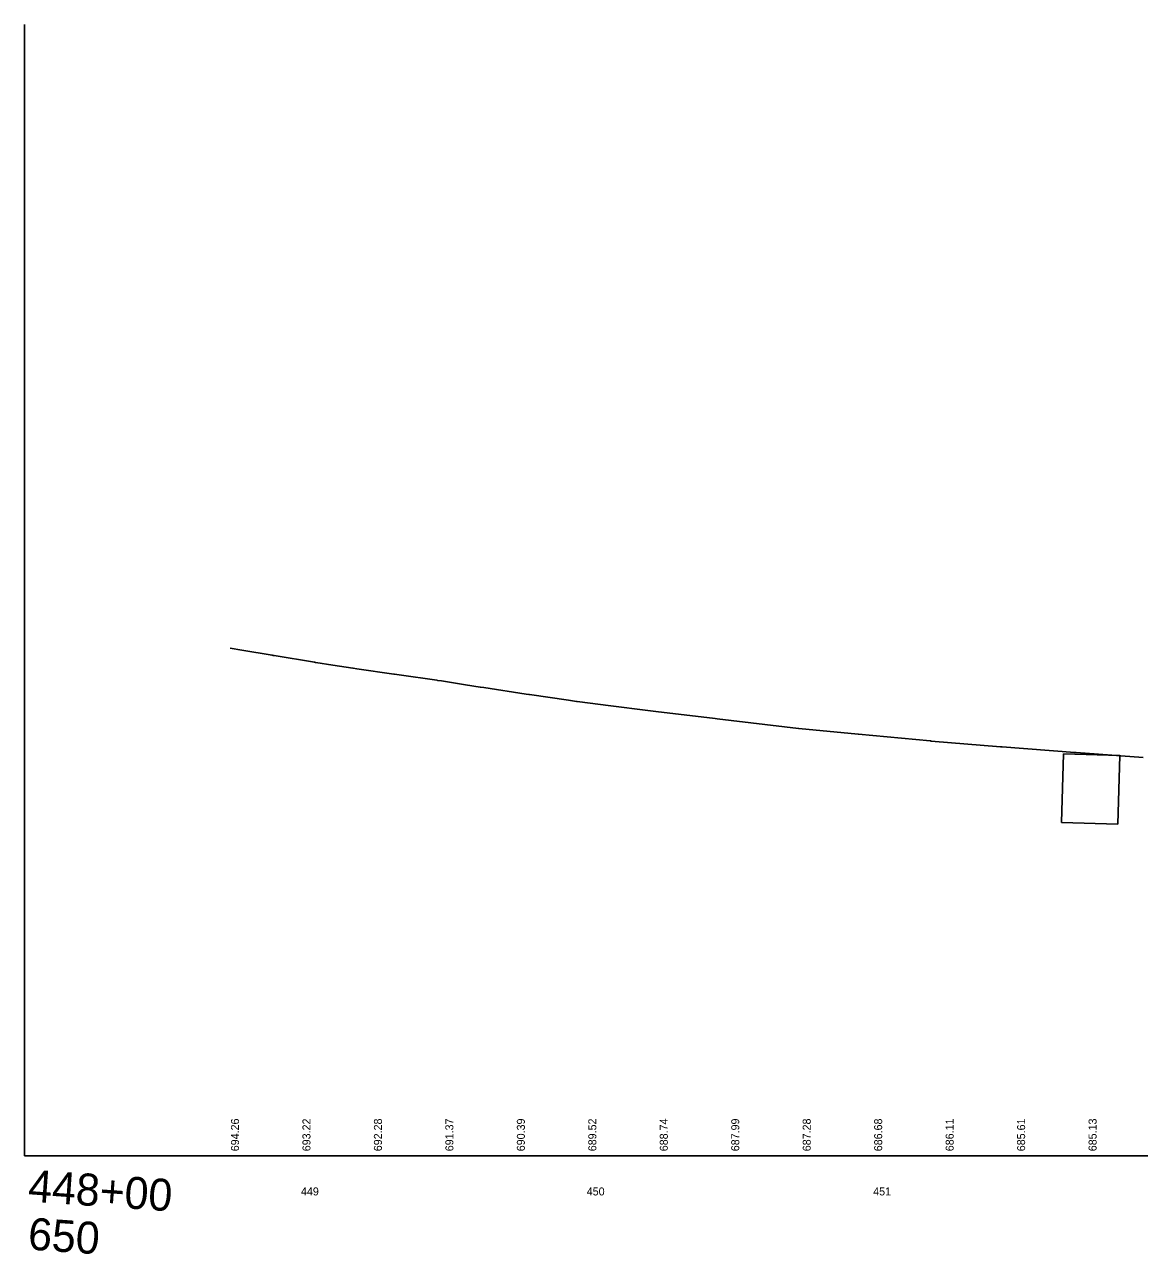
# Model space of a CAD drawing. Extents: x 157201 to 163282, y 424960 to 427200.
# Drawn here: x 161406.3 to 161796.3, y 425928.9 to 426359.1 of the extents above; entities that cross this region are included whole.
import ezdxf

# ---------------------------------------------------------------- set-up
doc = ezdxf.new("R2010")
doc.units = 0
for name, color, linetype in [('DR_X_Elev_Flow', 7, 'Continuous'), ('RD_X_Fence', 7, 'Continuous'), ('RD_X_GR_Rt', 7, 'Continuous'), ('SV_X_Shot_Marker', 7, 'Continuous'), ('UT_X_Water_Cells', 7, 'Continuous')]:
    doc.layers.add(name, color=color, linetype=linetype)

msp = doc.modelspace()

# ---------------------------------------------------------------- linework, layer by layer
at = {"layer": 'DR_X_Elev_Flow'}
for p, q in [((161769.01, 426079.96), (161769.74, 426103.95)), ((161769.74, 426103.95), (161789.44, 426103.35)), ((161788.71, 426079.36), (161789.44, 426103.35)), ((161769.01, 426079.96), (161788.71, 426079.36))]:
    msp.add_line(p, q, dxfattribs=at)
at = {"layer": 'SV_X_Shot_Marker'}
for q in [(161406.29, 426359.06), (162615.86, 425963.36)]:
    msp.add_line((161406.29, 425963.36), q, dxfattribs=at)
at = {"layer": 'UT_X_Water_Cells'}
msp.add_lwpolyline([(161478.17, 426140.9), (161482.27, 426140.23), (161492.93, 426138.44), (161493.22, 426138.39), (161493.48, 426138.34), (161493.56, 426138.33), (161507.74, 426136.02), (161508.07, 426135.96), (161508.12, 426135.95), (161508.15, 426135.94), (161514.08, 426135.05), (161521.08, 426133.96), (161521.17, 426133.94), (161521.27, 426133.93), (161522.55, 426133.75), (161535.5, 426131.87), (161535.69, 426131.84), (161537.37, 426131.62), (161550.48, 426129.72), (161550.6, 426129.7), (161550.73, 426129.69), (161552.18, 426129.47), (161560.53, 426128.16), (161565.7, 426127.33), (161565.71, 426127.33), (161565.72, 426127.33), (161565.73, 426127.33), (161566.99, 426127.14), (161581.8, 426124.85), (161582.63, 426124.72), (161582.69, 426124.72), (161582.76, 426124.72), (161582.87, 426124.71), (161596.61, 426122.74), (161599.38, 426122.33), (161599.41, 426122.32), (161599.64, 426122.29), (161611.42, 426120.82), (161624.35, 426119.17), (161627.08, 426118.84), (161647.91, 426116.32), (161648.51, 426116.25), (161677.07, 426112.9), (161677.13, 426112.9), (161697.86, 426110.86), (161698.05, 426110.84), (161723.08, 426108.5), (161723.23, 426108.48), (161723.37, 426108.47), (161747.7, 426106.44), (161747.73, 426106.44), (161748.23, 426106.41), (161773.66, 426104.43), (161774.19, 426104.4), (161797.53, 426102.67)], dxfattribs=at)

# ---------------------------------------------------------------- texts
at = {"layer": 'RD_X_Fence'}
for s, p in [('694.26', (161481.29, 425964.97)), ('693.22', (161506.29, 425964.97)), ('692.28', (161531.29, 425964.97)), ('691.37', (161556.29, 425964.97)), ('690.39', (161581.29, 425964.97)), ('689.52', (161606.29, 425964.97)), ('688.74', (161631.29, 425964.97)), ('687.99', (161656.29, 425964.97)), ('687.28', (161681.29, 425964.97)), ('686.68', (161706.29, 425964.97)), ('686.11', (161731.29, 425964.97)), ('685.61', (161756.29, 425964.97)), ('685.13', (161781.29, 425964.97))]:
    msp.add_text(s, height=2.8, rotation=90, dxfattribs=at).set_placement(p)
at = {"layer": 'RD_X_GR_Rt'}
for s, p in [('449', (161502.97, 425949.52)), ('450', (161602.94, 425949.52)), ('451', (161703.14, 425949.52))]:
    msp.add_text(s, height=2.8, dxfattribs=at).set_placement(p)
at = {"layer": 'SV_X_Shot_Marker'}
for s, p in [('448+00', (161407.3, 425947.42)), ('650', (161407.23, 425930.62))]:
    msp.add_text(s, height=11.198, rotation=356.0061, dxfattribs=at).set_placement(p)

doc.saveas('drawing.dxf')
